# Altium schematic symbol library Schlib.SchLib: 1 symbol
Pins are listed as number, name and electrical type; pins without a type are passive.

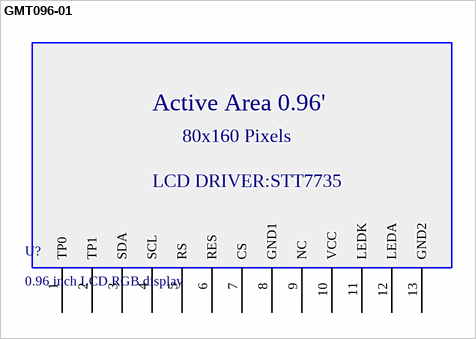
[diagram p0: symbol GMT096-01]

## GMT096-01
designator U?, comment 0.96 inch LCD RGB display
footprint GMT096-01
pins: 1 TP0, 2 TP1, 3 SDA, 4 SCL, 5 RS, 6 RES, 7 CS, 8 GND1, 9 NC, 10 VCC, 11 LEDK, 12 LEDA, 13 GND2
